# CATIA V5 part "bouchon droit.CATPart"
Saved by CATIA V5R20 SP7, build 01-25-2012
Part number: bouchon droit
Bounding box of the stored display mesh (mm): x 8.61 to 24.865, y -79 to -65, z -22.853 to -5.314
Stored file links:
  F:\Travaux\Modélisations\CFAO_2011\CFAO_2011_MMS\CFAO_2011_MMS_DONE\CFAO_2011_MMS_jboiteux\Catia\bouchon droit.CATPart
  U:\finthinkmotion\stepper.CATProduct
  F:\Travaux\Modélisations\CFAO_2011\CFAO_2011_MMS\CFAO_2011_MMS_DONE\CFAO_2011_MMS_jboiteux\Catia\bati.CATPart
  F:\Travaux\Modélisations\CFAO_2011\CFAO_2011_MMS\CFAO_2011_MMS_DONE\CFAO_2011_MMS_jboiteux\Catia\rondelle2 pied droit.CATPart
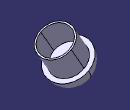
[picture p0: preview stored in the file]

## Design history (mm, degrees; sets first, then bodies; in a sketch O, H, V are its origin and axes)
Parameters
  rayontube = 9 mm {= External.royontubebati}
External parameters (linked from other documents)
  External.royontubebati = 9 mm
Set1
  DatumSurface1: linked copy from another document
  DatumCurve1 to DatumCurve3: linked copy from another document
Body1 (main body)
  Sketch1 on face of DatumSurface1, origin (-2.9622, 0, -5.1308), H (0, 1, 0), V (-0.866, 0, 0.5)
    projected circle E1 centre (-72, -21.4454) radius 5.5 from edge of DatumCurve1
    projected circle E2 centre (-72, -21.4454) radius 5 from edge of DatumCurve2
  Pad1: profile Sketch1, direction (0.5, 0, 0.866), length 9 {= rayontube}
  Sketch2 on start face of Pad1, origin (-2.9622, 0, -5.1308), H (0, -1, 0), V (-0.866, 0, 0.5)
    projected circle E1 centre (72, -21.4454) radius 7 from edge of DatumCurve3
  Pad2: profile Sketch2, direction (-0.5, 0, -0.866), length 7 {= rayontube *5/9+2mm}
  Fillet1: radius 7 {= rayontube *5/9 +2mm}, on edge [face of Pad2 from Sketch2.E1 | end face of Pad2]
